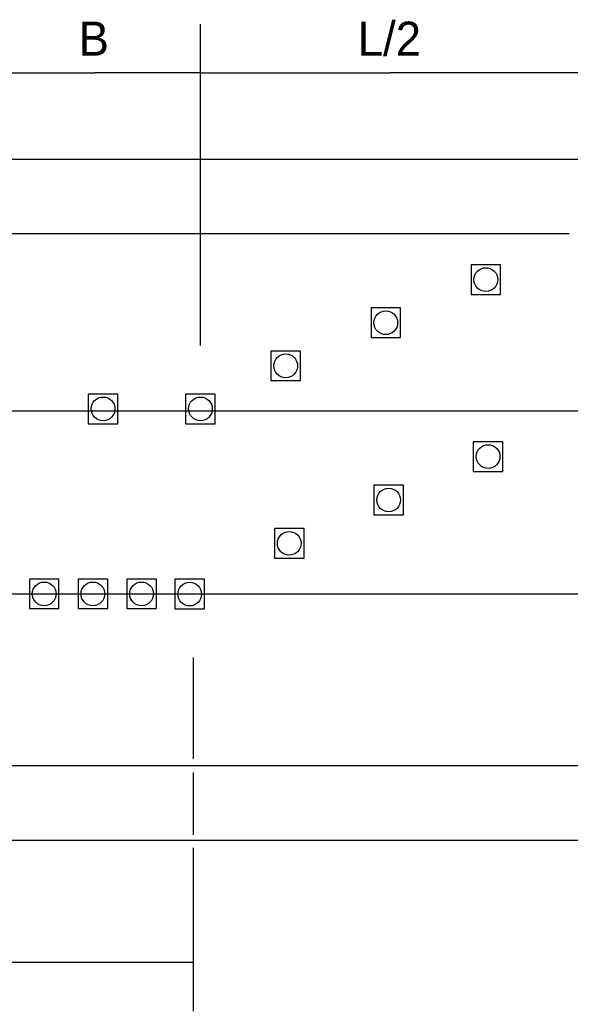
# Model space of a CAD drawing. Extents: x 99988 to 100172, y 99995 to 100047.
# Drawn here: x 100009.097 to 100010.227, y 100004.263 to 100006.301 of the extents above; entities that cross this region are included whole.
import ezdxf

# ---------------------------------------------------------------- set-up
doc = ezdxf.new("R2010")
doc.units = 0
for name, color, linetype in [('Default', 7, 'Continuous'), ('Level 15', 7, 'Continuous'), ('Level 20', 7, 'Continuous'), ('TR_WZ_TrafficSafetyCone', 7, 'Continuous'), ('TR_WZ_WorkZoneDetails', 7, 'Continuous')]:
    doc.layers.add(name, color=color, linetype=linetype)

msp = doc.modelspace()

# ---------------------------------------------------------------- linework, layer by layer
at = {"layer": 'Default'}
for p, q in [((100011.7483, 100005.4964), (100005.4457, 100005.4964)), ((100012.5819, 100005.1207), (100002.4254, 100005.1207))]:
    msp.add_line(p, q, dxfattribs=at)
at = {"layer": 'Level 15'}
for p, q in [((100009.0345, 100006.1922), (100009.2511, 100006.1922)), ((100009.4677, 100006.1922), (100009.2511, 100006.1922)), ((100009.4677, 100006.1922), (100009.8573, 100006.1922)), ((100010.2468, 100006.1922), (100009.8573, 100006.1922)), ((100009.4533, 100004.3634), (100008.2472, 100004.3634))]:
    msp.add_line(p, q, dxfattribs=at)
at = {"layer": 'TR_WZ_TrafficSafetyCone'}
for points in [[(100010.0235, 100005.7366), (100010.0842, 100005.7366), (100010.0842, 100005.7973), (100010.0235, 100005.7973)], [(100009.818, 100005.648), (100009.8787, 100005.648), (100009.8787, 100005.7088), (100009.818, 100005.7088)], [(100009.6125, 100005.5595), (100009.6732, 100005.5595), (100009.6732, 100005.6202), (100009.6125, 100005.6202)], [(100009.2373, 100005.4709), (100009.2981, 100005.4709), (100009.2981, 100005.5316), (100009.2373, 100005.5316)], [(100009.4373, 100005.4709), (100009.4981, 100005.4709), (100009.4981, 100005.5316), (100009.4373, 100005.5316)], [(100010.028, 100005.3729), (100010.0888, 100005.3729), (100010.0888, 100005.4337), (100010.028, 100005.4337)], [(100009.8239, 100005.2838), (100009.8846, 100005.2838), (100009.8846, 100005.3445), (100009.8239, 100005.3445)], [(100009.6197, 100005.1946), (100009.6805, 100005.1946), (100009.6805, 100005.2554), (100009.6197, 100005.2554)], [(100009.1164, 100005.0908), (100009.1772, 100005.0908), (100009.1772, 100005.1515), (100009.1164, 100005.1515)], [(100009.2164, 100005.0908), (100009.2772, 100005.0908), (100009.2772, 100005.1515), (100009.2164, 100005.1515)], [(100009.3164, 100005.0908), (100009.3772, 100005.0908), (100009.3772, 100005.1515), (100009.3164, 100005.1515)], [(100009.4152, 100005.0904), (100009.4759, 100005.0904), (100009.4759, 100005.1511), (100009.4152, 100005.1511)]]:
    msp.add_lwpolyline(points, close=True, dxfattribs=at)
for centre in [(100010.0538, 100005.767), (100009.8483, 100005.6784), (100009.6428, 100005.5898), (100009.2677, 100005.5013), (100009.4677, 100005.5013), (100010.0584, 100005.4033), (100009.8543, 100005.3141), (100009.6501, 100005.225), (100009.1468, 100005.1211), (100009.2468, 100005.1211), (100009.3468, 100005.1211), (100009.4456, 100005.1207)]:
    msp.add_circle(centre, 0.0244, dxfattribs=at)
at = {"layer": 'TR_WZ_WorkZoneDetails'}
for p, q in [((100009.4677, 100005.6316), (100009.4677, 100006.2922)), ((100011.7483, 100006.0142), (100008.2037, 100006.0142)), ((100010.225, 100005.8608), (100008.3165, 100005.8608)), ((100009.4533, 100004.7823), (100009.4533, 100004.9904)), ((100011.7483, 100004.7676), (100002.4278, 100004.7676)), ((100009.4533, 100004.6256), (100009.4533, 100004.7538)), ((100011.7483, 100004.6142), (100002.4307, 100004.6142)), ((100009.4533, 100004.2635), (100009.4533, 100004.5991))]:
    msp.add_line(p, q, dxfattribs=at)

# ---------------------------------------------------------------- texts
at = {"layer": 'Level 20'}
for s, p in [('B', (100009.2174, 100006.2272)), ('L/2', (100009.7906, 100006.2272))]:
    msp.add_text(s, height=0.07, dxfattribs=at).set_placement(p)

doc.saveas('drawing.dxf')
